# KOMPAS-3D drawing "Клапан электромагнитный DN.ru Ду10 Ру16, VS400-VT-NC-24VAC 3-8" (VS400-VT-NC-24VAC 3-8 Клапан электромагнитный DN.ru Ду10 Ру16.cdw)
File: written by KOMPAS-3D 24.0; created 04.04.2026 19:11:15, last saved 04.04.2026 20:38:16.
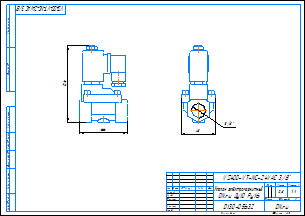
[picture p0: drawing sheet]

Document properties: c3d_UniqueCompID: ef56311e-7521-43dc-8291-0e6108b3d81d; Обозначение: VS400-ET-NC-220VAC 3-8; Наименование: Клапан электромагнитный DN.ru Ду10 Ру16; Автор: artio; Класс точности: c; Знак неуказанной шероховатости: Шероховатость не задана; Рассекать на разрезах: Да; Автор: artio; Форматы листов документа: A3; Полное имя файла: VS400-VT-NC-24VAC 3-8 Клапан электромагнитный DN.ru Ду10 Ру16.m3d; Масса: 0.797; Наименование: Клапан электромагнитный DN.ru Ду10 Ру16; Количество листов документа: 1; Примечание: D130-05632

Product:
- Body: Тело 1  | qty 1
    Масса: 1.030062
- Part/product: Клапан электромагнитный DN.ru Ду10 Ру16  | designation VS400-VT-NC-24VAC 3-8
    Масса: 0.797
    Раздел спецификации: Прочие изделия
    Примечание: D130-05632
    additional columns: ef56311e-7521-43dc-8291-0e6108b3d81d; VS400-ET-NC-220VAC 3-8; artio; c; Шероховатость не задана; Да

Views: Вид 1, Спереди, Проекционный вид 2
Referenced files in C:\Users\artio\OneDrive\Рабочий стол\Клапан электромагнитный DN.ru\VS400-ET-NC\VS400-ET-NC-24VDC\: VS400-ET-NC-24VDC 3-8 Клапан электромагнитный DN.ru Ду10 Ру16.m3d
Referenced files in C:\Users\artio\OneDrive\Рабочий стол\Клапан электромагнитный DN.ru\VS400-VT-NC\VS400-VT-NC-24VAC\: VS400-VT-NC-24VAC 3-8 Клапан электромагнитный DN.ru Ду10 Ру16.m3d
Referenced files in C:\Users\artio\OneDrive\Рабочий стол\Клапан электромагнитный DN.ru\VS400-ET-NC\: VS400-ET-NC-24VDC 3-8 Клапан электромагнитный DN.ru Ду10 Ру16.cdw
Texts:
  VS400-VT-NC-24VAC 3-8
  Клапан электромагнитный
  DN.ru Ду10 Ру16
  VS400-VT-NC-24VAC 3/8"
  VS400-VT-NC-24VAC 3/8"-
  Клапан электромагнитный DN.ru Ду10 Ру16
  VS400-VT-NC-24VAC 3-8 Клапан электромагнитный DN.ru Ду10 Ру16
Dimensions and other numbers on the sheet: 0; 3; 2; 4; 48; 3/8"; 66; 106; 1:1; 1; 0,8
